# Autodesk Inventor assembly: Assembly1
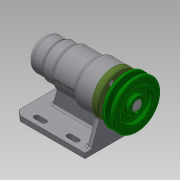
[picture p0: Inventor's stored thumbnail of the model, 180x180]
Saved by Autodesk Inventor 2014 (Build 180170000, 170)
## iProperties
Created: 2017-09
Part Number: Assembly1
Document SubType Name: Assembly
Designer: user
Author: user
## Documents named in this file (12)
- C:\Users\user\Desktop\시험\470908V1008\Assembly1.iam
- C:\Users\user\Documents\Inventor\470808V1024\Part1.ipt
- C:\Users\user\Desktop\시험\470908V1008\베어링 51202.ipt
- C:\Users\user\Desktop\시험\470908V1008\V벨트풀리.ipt
- C:\Users\user\Desktop\시험\470908V1008\멈춤나사 M3x8.ipt
- C:\Users\user\Desktop\시험\470908V1008\베어링 6004.ipt
- C:\Users\user\Desktop\시험\470908V1008\축.ipt
- C:\Users\user\Desktop\시험\470908V1008\키 5 x 5 x 16.ipt
- C:\Users\user\Desktop\시험\470908V1008\커버.ipt
- C:\Users\user\Desktop\시험\470908V1008\오일 실 20x35x7.ipt
- C:\Users\user\Desktop\시험\470908V1008\어댑터슬리브.ipt
- C:\Users\user\Desktop\시험\470908V1008\볼트 M4 x 12.ipt
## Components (2 placed, 2 different names)
1. Part1:1 — Rotational:7
2. V벨트풀리:1 — Rigid:1
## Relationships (2: WeldJoint 1, RevoluteJoint 1)
- Rigid:1 [WeldJoint]: V벨트풀리:1
- Rotational:7 [RevoluteJoint]: Part1:1
